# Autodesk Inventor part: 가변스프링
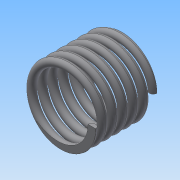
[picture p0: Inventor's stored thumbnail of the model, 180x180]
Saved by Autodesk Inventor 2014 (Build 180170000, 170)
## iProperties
Created: 2019-07
Part Number: 가변스프링
Material: 일반
Document SubType Name: Modeling
Designer: net
Density: 1 g/cm^3
Appearance: 기본값
Mass: 0.980232 g
Surface Area: 20.008 cm^2
Volume: 0.980232 cm^3
Author: net
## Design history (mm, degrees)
sketch "스케치1"
  geometry: L1 (0, 0)-(8.5, 0); L2 (8.5, 0)-(8.5, -16); L3 (8.5, -16)-(0, -16); L4 (0, -16)-(0, 0); C1 r 1 at (8.5, 0)
  constraints: 8 end point, 2 parallel, 1 centre point, 1 coincident, 1 horizontal, 1 perpendicular
  dimensions: "d0" = 17 diameter of L2 L4; "d1" = 16 distance of L1.end L2.end (derived); "d2" = 2 diameter of C1
feature "코일1" pitch "d3" = 10; turns "d5" = 6; dims "d4" = 16 (= d1), "d6" = 0, angle "d7" = 90 deg, angle "d8" = 90 deg, "d9" = 0, "d10" = 0
node "작업 평면1"
node "작업 평면2"
sketch "스케치2"
  geometry: L1 (-1, 0)-(1, 0) reference; 1 further point
  constraints: 1 horizontal alignment
extrude "돌출1" cut sketch "스케치2" stored distance "d13" = 10; taper "d14" = 0 deg
sketch "스케치3"
  geometry: L1 (7.5, 0)-(9.5, 0) reference; 1 further point
  constraints: 1 horizontal alignment
extrude "돌출2" cut sketch "스케치3" stored distance "d15" = 10; taper "d16" = 0 deg
node "솔리드1"
node "절단 모서리 투영1"
node "절단 모서리 투영2"
other parameters: "d11" = 90 deg, "d12" = 90 deg
